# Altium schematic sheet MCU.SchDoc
size A4; Revision: B.2
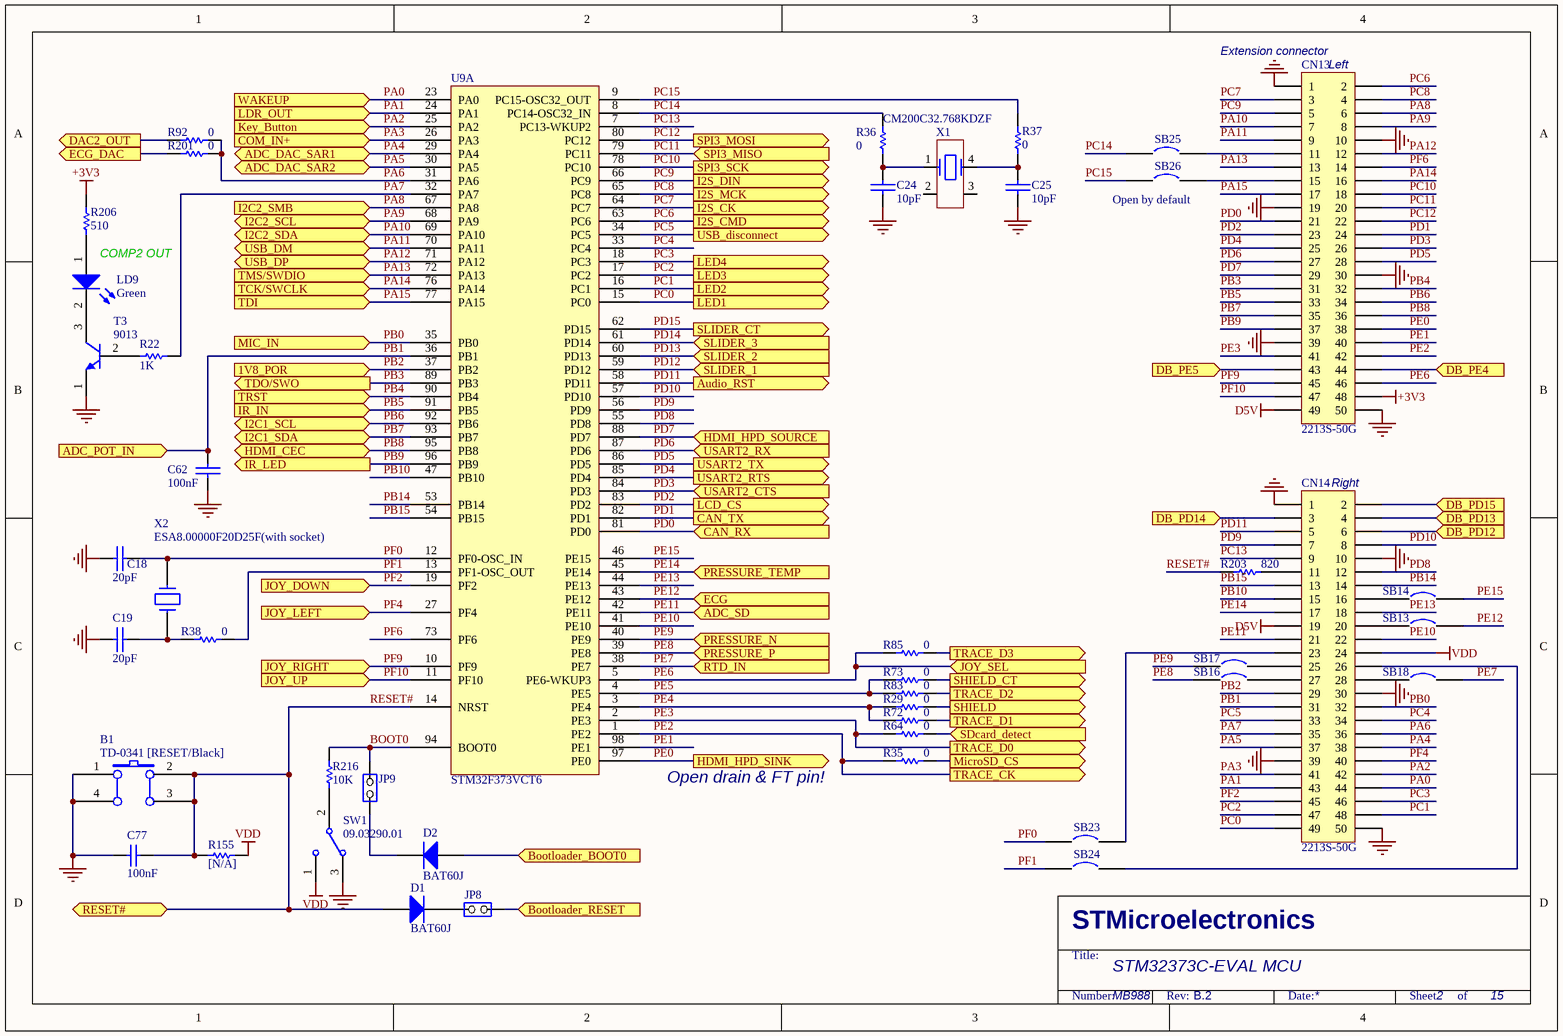
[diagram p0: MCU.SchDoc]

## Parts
B1  TD-0341 [RESET/Black]  [PB10]
C18  20pF  [0603C]
C19  20pF  [0603C]
C24  10pF  [0603C]
C25  10pF  [0603C]
C62  100nF  [0603C]
C77  100nF  [0603C]
CN13  2213S-50G  [2*25P]
CN14  2213S-50G  [2*25P]
D1  BAT60J  [SOD-323]
D2  BAT60J  [SOD-323]
JP8  (no value)  [SIP2]
JP9  (no value)  [SIP2]
LD9  Green  [0603D]
R22  1K  [0603R]
R29  0  [0603R]
R35  0  [0603R]
R36  0  [0603R]
R37  0  [0603R]
R38  0  [0603R]
R64  0  [0603R]
R72  0  [0603R]
R73  0  [0603R]
R83  0  [0603R]
R85  0  [0603R]
R92  0  [0603R]
R155  [N/A]  [0603R]
R201  0  [0603R]
R203  820  [0603R]
R206  510  [0603R]
R216  10K  [0603R]
SB13  (no value)  [JP2_SMD]
SB14  (no value)  [JP2_SMD]
SB16  (no value)  [JP2_SMD]
SB17  (no value)  [JP2_SMD]
SB18  (no value)  [JP2_SMD]
SB23  (no value)  [JP2_SMD]
SB24  (no value)  [JP2_SMD]
SB25  (no value)  [JP2_SMD]
SB26  (no value)  [JP2_SMD]
SW1  09.03290.01  [SIP3]
T3  9013  [SOT-23]
U9  STM32F373VCT6  [IC149-100-025-B5]  (part A of 2)
X1  CM200C32.768KDZF  [SM8]
X2  ESA8.00000F20D25F(with socket)  [XTAL_socket]

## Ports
1V8_POR (in), ADC_DAC_SAR1 (bidir), ADC_DAC_SAR2 (bidir), ADC_POT_IN (in), ADC_SD (in), Audio_RST (out), Bootloader_BOOT0 (in), Bootloader_RESET (in), CAN_RX (in), CAN_TX (out), COM_IN+ (in), DAC2_OUT (out), DB_PD12 (in), DB_PD13 (in), DB_PD14 (in), DB_PD15 (in), DB_PE4 (in), DB_PE5 (in), ECG (in), ECG_DAC (out), HDMI_CEC (bidir), HDMI_HPD_SINK (out), HDMI_HPD_SOURCE (in), I2C1_SCL (bidir), I2C1_SDA (bidir), I2C2_SCL (bidir), I2C2_SDA (bidir), I2C2_SMB (in), I2S_CK (out), I2S_CMD (out), I2S_DIN (out), I2S_MCK (out), IR_IN (in), IR_LED (out), JOY_DOWN (in), JOY_LEFT (in), JOY_RIGHT (in), JOY_SEL (in), JOY_UP (in), Key_Button (in), LCD_CS (out), LDR_OUT (in), LED1 (out), LED2 (out), LED3 (out), LED4 (out), MIC_IN (in), MicroSD_CS (out), PRESSURE_N (in), PRESSURE_P (in), PRESSURE_TEMP (in), RESET# (bidir), RTD_IN (in), SDcard_detect (in), SHIELD (out), SHIELD_CT (out), SLIDER_1 (in), SLIDER_2 (in), SLIDER_3 (in), SLIDER_CT (out), SPI3_MISO (in), SPI3_MOSI (out), SPI3_SCK (out), TCK/SWCLK (in), TDI (in), TDO/SWO (out), TMS/SWDIO (in), TRACE_CK (out), TRACE_D0 (out), TRACE_D1 (out), TRACE_D2 (out), TRACE_D3 (out), TRST (in), USART2_CTS (in), USART2_RTS (out), USART2_RX (in), USART2_TX (out), USB_disconnect (out), USB_DM (bidir), USB_DP (bidir), WAKEUP (in)

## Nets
+3V3: CN13.48 R206.1
D5V: CN13.49 CN14.19
GND: B1.1(A0) B1.4(A1) C18.2 C19.2 C24.2 C25.2 C62.1 C77.1 CN13.1 CN13.10 CN13.19 CN13.30 CN13.39 CN13.50 CN14.1 CN14.10 CN14.30 CN14.39 CN14.50 SW1.3 T3.1(E)
VDD: CN14.24 R155.2 SW1.1
BOOT0: JP9.2(NO) R216.1 U9.94(BOOT0)
Bootloader_BOOT0: D2.1(A) ; port Bootloader_BOOT0
Bootloader_RESET: JP8.2(NO) ; port Bootloader_RESET
DAC2_OUT: R92.2 ; port DAC2_OUT
DB_PD12: CN14.6 ; port DB_PD12
DB_PD13: CN14.4 ; port DB_PD13
DB_PD14: CN14.3 ; port DB_PD14
DB_PD15: CN14.2 ; port DB_PD15
DB_PE4: CN13.44 ; port DB_PE4
DB_PE5: CN13.43 ; port DB_PE5
ECG_DAC: R201.2 ; port ECG_DAC
MicroSD_CS: R35.1 ; port MicroSD_CS
PA0: CN14.44 U9.23(PA0) ; port WAKEUP
PA1: CN14.43 U9.24(PA1) ; port LDR_OUT
PA2: CN14.42 U9.25(PA2) ; port Key_Button
PA3: CN14.41 U9.26(PA3) ; port COM_IN+
PA4: CN14.38 U9.29(PA4) ; port ADC_DAC_SAR1
PA5: CN14.37 U9.30(PA5) ; port ADC_DAC_SAR2
PA6: CN14.36 R92.1 R201.1 U9.31(PA6)
PA7: CN14.35 R22.2 U9.32(PA7)
PA8: CN13.6 U9.67(PA8) ; port I2C2_SMB
PA9: CN13.8 U9.68(PA9) ; port I2C2_SCL
PA10: CN13.7 U9.69(PA10) ; port I2C2_SDA
PA11: CN13.9 U9.70(PA11) ; port USB_DM
PA12: CN13.12 U9.71(PA12) ; port USB_DP
PA13: CN13.13 U9.72(PA13) ; port TMS/SWDIO
PA14: CN13.16 U9.76(PA14) ; port TCK/SWCLK
PA15: CN13.17 U9.77(PA15) ; port TDI
PB0: CN14.32 U9.35(PB0) ; port MIC_IN
PB1: C62.2 CN14.31 U9.36(PB1) ; port ADC_POT_IN
PB2: CN14.29 U9.37(PB2) ; port 1V8_POR
PB3: CN13.31 U9.89(PB3) ; port TDO/SWO
PB4: CN13.32 U9.90(PB4) ; port TRST
PB5: CN13.33 U9.91(PB5) ; port IR_IN
PB6: CN13.34 U9.92(PB6) ; port I2C1_SCL
PB7: CN13.35 U9.93(PB7) ; port I2C1_SDA
PB8: CN13.36 U9.95(PB8) ; port HDMI_CEC
PB9: CN13.37 U9.96(PB9) ; port IR_LED
PB10: CN14.15 U9.47(PB10)
PB14: CN14.14 U9.53(PB14)
PB15: CN14.13 U9.54(PB15)
PC0: CN14.49 U9.15(PC0) ; port LED1
PC1: CN14.48 U9.16(PC1) ; port LED2
PC2: CN14.47 U9.17(PC2) ; port LED3
PC3: CN14.46 U9.18(PC3) ; port LED4
PC4: CN14.34 U9.33(PC4)
PC5: CN14.33 U9.34(PC5) ; port USB_disconnect
PC6: CN13.2 U9.63(PC6) ; port I2S_CMD
PC7: CN13.3 U9.64(PC7) ; port I2S_CK
PC8: CN13.4 U9.65(PC8) ; port I2S_MCK
PC9: CN13.5 U9.66(PC9) ; port I2S_DIN
PC10: CN13.18 U9.78(PC10) ; port SPI3_SCK
PC11: CN13.20 U9.79(PC11) ; port SPI3_MISO
PC12: CN13.22 U9.80(PC12) ; port SPI3_MOSI
PC13: CN14.9 U9.7(PC13-WKUP2)
PC14: R36.2 SB25.1 U9.8(PC14-OSC32_IN)
PC15: R37.2 SB26.1 U9.9(PC15-OSC32_OUT)
PD0: CN13.21 U9.81(PD0) ; port CAN_RX
PD1: CN13.24 U9.82(PD1) ; port CAN_TX
PD2: CN13.23 U9.83(PD2) ; port LCD_CS
PD3: CN13.26 U9.84(PD3) ; port USART2_CTS
PD4: CN13.25 U9.85(PD4) ; port USART2_RTS
PD5: CN13.28 U9.86(PD5) ; port USART2_TX
PD6: CN13.27 U9.87(PD6) ; port USART2_RX
PD7: CN13.29 U9.88(PD7) ; port HDMI_HPD_SOURCE
PD8: CN14.12 U9.55(PD8)
PD9: CN14.7 U9.56(PD9)
PD10: CN14.8 U9.57(PD10)
PD11: CN14.5 U9.58(PD11) ; port Audio_RST
PD12: U9.59(PD12) ; port SLIDER_1
PD13: U9.60(PD13) ; port SLIDER_2
PD14: U9.61(PD14) ; port SLIDER_3
PD15: U9.62(PD15) ; port SLIDER_CT
PE0: CN13.38 U9.97(PE0) ; port HDMI_HPD_SINK
PE1: CN13.40 U9.98(PE1)
PE2: CN13.42 R35.2 U9.1(PE2) ; port TRACE_CK
PE3: CN13.41 R64.2 U9.2(PE3) ; port TRACE_D0
PE4: R29.2 R72.2 U9.3(PE4)
PE5: R73.2 R83.2 U9.4(PE5)
PE6: CN13.46 R85.2 U9.5(PE6-WKUP3) ; port JOY_SEL
PE7: SB18.2 U9.38(PE7) ; port RTD_IN
PE8: SB16.1 U9.39(PE8) ; port PRESSURE_P
PE9: SB17.1 U9.40(PE9) ; port PRESSURE_N
PE10: CN14.22 U9.41(PE10)
PE11: CN14.21 U9.42(PE11) ; port ADC_SD
PE12: SB13.2 U9.43(PE12) ; port ECG
PE13: CN14.18 U9.44(PE13)
PE14: CN14.17 U9.45(PE14) ; port PRESSURE_TEMP
PE15: SB14.2 U9.46(PE15)
PF0: C18.1 SB23.1 U9.12(PF0-OSC_IN) X2.2
PF1: R38.1 SB24.1 U9.13(PF1-OSC_OUT)
PF2: CN14.45 U9.19(PF2) ; port JOY_DOWN
PF4: CN14.40 U9.27(PF4) ; port JOY_LEFT
PF6: CN13.14 U9.73(PF6)
PF9: CN13.45 U9.10(PF9) ; port JOY_RIGHT
PF10: CN13.47 U9.11(PF10) ; port JOY_UP
RESET#: B1.2(B0) B1.3(B1) C77.2 D1.1(A) R155.1 R203.2 U9.14(NRST) ; port RESET#
SDcard_detect: R64.1 ; port SDcard_detect
SHIELD: R29.1 ; port SHIELD
SHIELD_CT: R73.1 ; port SHIELD_CT
TRACE_D1: R72.1 ; port TRACE_D1
TRACE_D2: R83.1 ; port TRACE_D2
TRACE_D3: R85.1 ; port TRACE_D3
NetC19_1: C19.1 R38.2 X2.1
NetC24_1: C24.1 R36.1 X1.1
NetC25_1: C25.1 R37.1 X1.4
NetCN13_11: CN13.11 SB25.2
NetCN13_15: CN13.15 SB26.2
NetCN14_11: CN14.11 R203.1
NetCN14_16: CN14.16 SB14.1
NetCN14_20: CN14.20 SB13.1
NetCN14_23: CN14.23 SB23.2
NetCN14_25: CN14.25 SB17.2
NetCN14_26: CN14.26 SB24.2
NetCN14_27: CN14.27 SB16.2
NetCN14_28: CN14.28 SB18.1
NetD1_2: D1.2(K) JP8.1(COMMON)
NetD2_2: D2.2(K) JP9.1(COMMON)
NetLD9_1: LD9.1(A) R206.2
NetLD9_2: LD9.2(K) T3.3(C)
NetR22_1: R22.1 T3.2(B)
NetR216_2: R216.2 SW1.2

Not connected (* = marked no-connect by the designer): X1 2 3

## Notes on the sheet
- (near CN13) Extension connector
- (near CN13) Left
- (near SB26) Open by default
- COMP2 OUT
- (near CN14) Right
- Open drain & FT pin!
- STM32373C-EVAL MCU
- MB988
- 2
- 15

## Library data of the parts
B1 = SW PUSHBUTTON: SE PUSHBUTTON
C18 C19 C24 C25 C62 = CAP: Capacitor
C77 = CAP: Capacitor; Value: 100pF
CN13 CN14 = Header 25X2: Header, 25-Pin, Dual row
D1 D2 = Diode: Default Diode; Code - JEDEC: DO-214-AB
JP8 JP9 = JP2
LD9 = LED2: Typical RED, GREEN, YELLOW, AMBER GaAs LED
R22 = Res1: Resistor
R29 R35-R38 R64 R72 R73 R83 R85 R92 R201 R203 R206 = Res1: Resistor; Value: 1K
R155 R216 = res1: Resistor; Value: 1K
SB13 SB14 SB16-SB18 SB23-SB26 = Circuit Breaker
SW1 = SW-SPDT: SPDT Subminiature Toggle Switch, Right Angle Mounting, Vertical Actuation; Revision 1: Jul-2002: Re-released for DXP Platform.; Revision 2: 17-Dec-2003: Schematic revised, PCB Footprint replaced.
T3 = NPN: NPN Bipolar Transistor; Code - JEDEC: TO-226-AA
U9 = Goldfish
X1 = MC306
X2 = CRYSTAL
